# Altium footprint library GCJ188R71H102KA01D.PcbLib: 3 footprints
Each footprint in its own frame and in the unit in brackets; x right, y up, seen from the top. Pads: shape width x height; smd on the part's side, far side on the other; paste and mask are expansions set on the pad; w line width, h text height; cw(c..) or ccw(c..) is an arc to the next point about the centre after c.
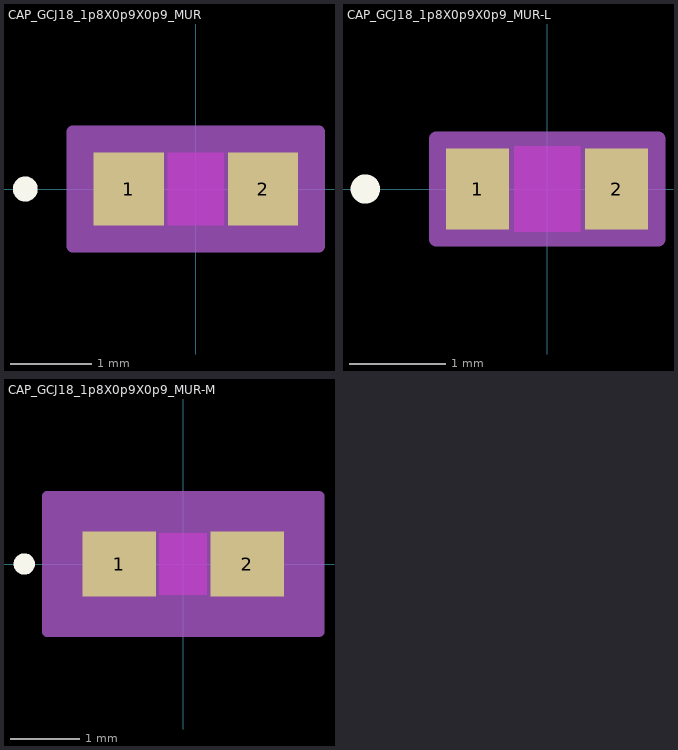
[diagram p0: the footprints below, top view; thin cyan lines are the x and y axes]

## CAP_GCJ18_1p8X0p9X0p9_MUR [mil]
pads (2):
  rect 33.78x35 smd paste+0 mask+0: 1(-32.39,0) 2(32.39,0)
Top Layer keep-out:
  region: -13.5,-15.5 -13.5,15.5 13.5,15.5 13.5,-15.5
Top Overlay:
  circle w6: c-82.28,0 r3
  text ".Designator" at -137.5,-25 h50
Keep-Out Layer:
  region: -13.5,-17.5 -13.5,17.5 13.5,17.5 13.5,-17.5
Mechanical 13:
  circle w1: c-27.39,0 r3
  lines w1: -35.5,-17.5 -35.5,17.5 ; -35.5,-17.5 -15.5,-17.5 -15.5,17.5 -35.5,17.5 ; -35.5,-17.5 35.5,-17.5 ; -35.5,-17.5 -35.5,17.5 ; -35.5,17.5 35.5,17.5 ; 35.5,-17.5 15.5,-17.5 15.5,17.5 35.5,17.5 ; 35.5,-17.5 35.5,17.5 ; 35.5,-17.5 35.5,17.5
  text ".Designator" at -137.5,-25 h50
Mechanical 15:
  region: 59.28,-27.5 -59.28,-27.5 -59.28,27.5 59.28,27.5
  lines w6: -59.28,-27.5 -59.28,27.5 59.28,27.5 59.28,-27.5 -59.28,-27.5
3D body "CAP_GCJ18_1p8X0p9X0p9_MUR.step": height 35, standoff 0, extent -35.51,-17.48 35.51,17.48

## CAP_GCJ18_1p8X0p9X0p9_MUR-L [mil]
pads (2):
  rect 25.91x33.03 smd paste+0 mask+0: 1(-28.45,0) 2(28.45,0)
Top Layer keep-out:
  region: -13.5,-15.5 -13.5,15.5 13.5,15.5 13.5,-15.5
Top Overlay:
  circle w6: c-74.41,0 r3
  text ".Designator" at -137.5,-25 h50
Keep-Out Layer:
  region: -13.5,-17.5 -13.5,17.5 13.5,17.5 13.5,-17.5
Mechanical 13:
  circle w1: c-23.45,0 r3
  lines w1: -35.5,-17.5 -35.5,17.5 ; -35.5,-17.5 -15.5,-17.5 -15.5,17.5 -35.5,17.5 ; -35.5,-17.5 35.5,-17.5 ; -35.5,-17.5 -35.5,17.5 ; -35.5,17.5 35.5,17.5 ; 35.5,-17.5 15.5,-17.5 15.5,17.5 35.5,17.5 ; 35.5,-17.5 35.5,17.5 ; 35.5,-17.5 35.5,17.5
  text ".Designator" at -137.5,-25 h50
Mechanical 15:
  region: 45.41,-20.52 -45.41,-20.52 -45.41,20.52 45.41,20.52
  lines w6: -45.41,-20.52 -45.41,20.52 45.41,20.52 45.41,-20.52 -45.41,-20.52
3D body "CAP_GCJ18_1p8X0p9X0p9_MUR.step": height 35, standoff 0, extent -35.51,-17.48 35.51,17.48

## CAP_GCJ18_1p8X0p9X0p9_MUR-M [mil]
pads (2):
  rect 41.65x36.97 smd paste+0 mask+0: 1(-36.33,0) 2(36.33,0)
Top Layer keep-out:
  region: -13.5,-15.5 -13.5,15.5 13.5,15.5 13.5,-15.5
Top Overlay:
  circle w6: c-90.15,0 r3
  text ".Designator" at -137.5,-25 h50
Keep-Out Layer:
  region: -13.5,-17.5 -13.5,17.5 13.5,17.5 13.5,-17.5
Mechanical 13:
  circle w1: c-31.33,0 r3
  lines w1: -35.5,-17.5 -35.5,17.5 ; -35.5,-17.5 -15.5,-17.5 -15.5,17.5 -35.5,17.5 ; -35.5,-17.5 35.5,-17.5 ; -35.5,-17.5 -35.5,17.5 ; -35.5,17.5 35.5,17.5 ; 35.5,-17.5 15.5,-17.5 15.5,17.5 35.5,17.5 ; 35.5,-17.5 35.5,17.5 ; 35.5,-17.5 35.5,17.5
  text ".Designator" at -137.5,-25 h50
Mechanical 15:
  region: 77.15,-38.48 -77.15,-38.48 -77.15,38.48 77.15,38.48
  lines w6: -77.15,-38.48 -77.15,38.48 77.15,38.48 77.15,-38.48 -77.15,-38.48
3D body "CAP_GCJ18_1p8X0p9X0p9_MUR.step": height 35, standoff 0, extent -35.51,-17.48 35.51,17.48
